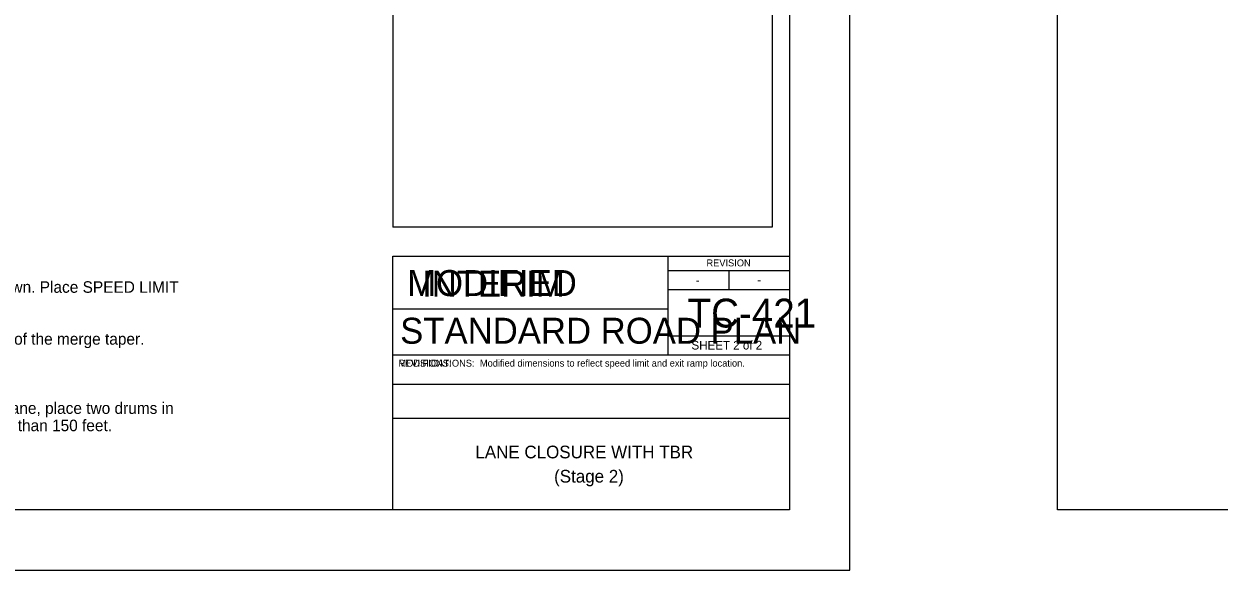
# Model space of a CAD drawing. Extents: x 10133 to 81668, y 4177 to 11018.
# Drawn here: x 29940 to 32012, y 7820 to 8767 of the extents above; entities that cross this region are included whole.
import ezdxf

# ---------------------------------------------------------------- set-up
doc = ezdxf.new("R2010")
doc.units = 0
for name, color, linetype in [('dsnShtPlotShapeBatchPrint', 7, 'Continuous'), ('dsnstdblockInterim', 7, 'Continuous'), ('dsnStdBlockModified', 7, 'Continuous'), ('dsnStdBorder', 7, 'Continuous'), ('Level 1', 7, 'Continuous'), ('SheetBorder', 7, 'Continuous'), ('StdDetailLabel', 7, 'Continuous'), ('StdDimension', 7, 'Continuous'), ('StdNote', 7, 'Continuous'), ('StdNoteLinks', 7, 'Continuous')]:
    doc.layers.add(name, color=color, linetype=linetype)

msp = doc.modelspace()

# ---------------------------------------------------------------- linework, layer by layer
at = {"layer": 'dsnShtPlotShapeBatchPrint'}
for p, q in [((30579.5, 9884), (30579.5, 8414)), ((31237.5, 9884), (31237.5, 8414)), ((31237.5, 8414), (30579.5, 8414))]:
    msp.add_line(p, q, dxfattribs=at)
at = {"layer": 'dsnstdblockInterim'}
msp.add_lwpolyline([(30579.5, 8364), (31267.5, 8364), (31267.5, 7924), (30579.5, 7924)], close=True, dxfattribs=at)
at = {"layer": 'dsnStdBlockModified'}
msp.add_lwpolyline([(28132.5, 9934), (31267.5, 9934), (31267.5, 7924), (28132.5, 7924)], close=True, dxfattribs=at)
at = {"layer": 'dsnStdBorder'}
msp.add_lwpolyline([(28028, 7819.5), (31372, 7819.5), (31372, 10403.5), (28028, 10403.5)], close=True, dxfattribs=at)
at = {"layer": 'SheetBorder'}
for points in [[(28132.5, 9944), (31267.5, 9944), (31267.5, 7924), (28132.5, 7924)], [(31732.5, 9944), (34867.5, 9944), (34867.5, 7924), (31732.5, 7924)]]:
    msp.add_lwpolyline(points, close=True, dxfattribs=at)
at = {"layer": 'StdNoteLinks'}
for p, q in [((31056.6, 8364), (31056.6, 8272.7)), ((31056.6, 8339.1), (31267.5, 8339.1)), ((31162.1, 8339.1), (31162.1, 8305.9)), ((31056.6, 8305.9), (31267.5, 8305.9)), ((30579.5, 8272.7), (31056.6, 8272.7)), ((31056.6, 8272.7), (31056.6, 8192.7)), ((31267.5, 8224.9), (31056.6, 8224.9)), ((30579.5, 8192.7), (31267.5, 8192.7)), ((30579.5, 8141.7), (31267.5, 8141.7)), ((30579.5, 8082.7), (31267.5, 8082.7))]:
    msp.add_line(p, q, dxfattribs=at)
msp.add_lwpolyline([(30579.5, 8364), (31267.5, 8364), (31267.5, 7924), (30579.5, 7924)], close=True, dxfattribs=at)

# ---------------------------------------------------------------- texts
at = {"layer": 'Level 1'}
for s, p in [('Place SPEED LIMIT AHEAD sign and SPEED LIMIT 55 sign prior to the lane closure as shown. Place SPEED LIMIT', (28828.9, 8300.4)), ('For traffic control zones lasting more than 4 hours, place a Speed Feedback Sign at the end of the merge taper.', (28828.9, 8210.4)), ('For lanes closed to traffic, place two drums every 1000 feet. For full depth excavations in a closed lane, place two drums in ', (28748.9, 8090.4)), ('front of each location. Additional drums need not be placed for full depth excavations spaced closer than 150 feet.', (28748.9, 8060.4))]:
    msp.add_text(s, height=20, dxfattribs=at).set_placement(p)
at = {"layer": 'StdDetailLabel'}
msp.add_text('INTERIM', height=45, dxfattribs=at).set_placement((30630.5, 8293.7))
at = {"layer": 'StdDimension'}
for s, height, p in [('MODIFIED', 45, (30604.6, 8294.8)), ('MODIFICATIONS:', 12, (30589.5, 8172.3))]:
    msp.add_text(s, height=height, dxfattribs=at).set_placement(p)
at = {"layer": 'StdNote'}
msp.add_text('REVISIONS:', height=12, dxfattribs=at).set_placement((30589.5, 8172.3))
at = {"layer": 'StdNoteLinks'}
for s, height, p in [('REVISION', 12, (31123.6, 8346.2)), ('-', 15, (31105.1, 8314.7)), ('-', 15, (31211.6, 8315.1)), ('TC-421', 50, (31090.9, 8240.2)), ('STANDARD ROAD PLAN', 45.001, (30592.5, 8212.1)), ('SHEET 2 of 2', 15, (31097.6, 8202)), ('Modified dimensions to reflect speed limit and exit ramp location.', 12, (30730.8, 8172.4)), ('LANE CLOSURE WITH TBR', 22, (30722.9, 8013.3)), ('(Stage 2)', 22, (30859.4, 7971.3))]:
    msp.add_text(s, height=height, dxfattribs=at).set_placement(p)

doc.saveas('drawing.dxf')
